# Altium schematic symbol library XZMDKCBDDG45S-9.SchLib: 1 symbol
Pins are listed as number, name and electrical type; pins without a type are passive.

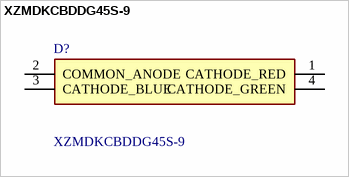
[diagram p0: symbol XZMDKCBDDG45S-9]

## XZMDKCBDDG45S-9
designator D?
LED RGB CLEAR 4SMD GW; Manufacturer_Name: SunLED; Geometry.Height: 2.1mm
footprint XZMDKCBDDG45S9
pins: 1 CATHODE_RED, 2 COMMON_ANODE, 3 CATHODE_BLUE, 4 CATHODE_GREEN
